(* Logix 5000 project; controller ControlLogix 1756-L63 rev 16.20; software revision 16.04 *)

TASK MainTask (continuous, watchdog 500 ms) : MainProgram

MODULES
   Local : 1756-L63 (ICP 0, rev 16.20)
      EGD : vendor 1 type 0 code 15 (ICP 1, rev 1.1, Output RPI 5 ms)
END_MODULES

TYPE Backplane :   // Values used by program for data transfer operation between the module and the processor.
STRUCT
   LastRead : INT;   // Index of last read block
   LastWrite : INT;   // Index of last write block
   BlockIndex : INT;   // Computed block offset for data table
   StatusIndex : INT;   // Computed block offset for status data
   ReadDataBlkCount : INT;   // Holds the value of the Block Counts of the Read Data Array. Array Size is divided by 200.
   WriteDataBlkCount : INT;   // Holds the value of the Block Counts of the Write Data Array. Array Size is divided by 200.
   RBTSremainder : INT;   // Holds remainder calculation value from the read array.
   WBTSremainder : INT;   // Holds remainder calculation value from the write array.
   ReadDataSizeGet : INT;   // Holds read data array size.
   WriteDataSizeGet : INT;   // Holds write data array size.
END_STRUCT
END_TYPE

TYPE Blk9250Stat :   // Block 9250 Response Block general status
STRUCT
   BlkWriteIDreq : INT;   // Block Write ID Requested
   PassCnt : INT;   // Program Scan Counter
   ProdCodeByte0 : SINT;   // Product code byte 0 of 0 & 1
   ProdCodeByte1 : SINT;   // Product code byte 1 of 0 & 1
   ProdCodeByte2 : SINT;   // Product code byte 2 of 2 & 3
   ProdCodeByte3 : SINT;   // Product code byte 3 of 2 & 3
   RevByte0 : SINT;   // Revision byte 0 of 0 & 1
   RevByte1 : SINT;   // Revision byte 1 of 0 & 1
   RevByte2 : SINT;   // Revision byte 2 of 2 & 3
   RevByte3 : SINT;   // Revision byte 3 of 2 & 3
   OpByte0 : SINT;   // Op byte 0 of 0 & 1
   OpByte1 : SINT;   // Op byte 1 of 0 & 1
   OpByte2 : SINT;   // Op byte 2 of 2 & 3
   OpByte3 : SINT;   // Op byte 3 of 2 & 3
   RunByte0 : SINT;   // Run byte 0 of 0 & 1
   RunByte1 : SINT;   // Run byte 1 of 0 & 1
   RunByte2 : SINT;   // Run byte 2 of 2 & 3
   RunByte3 : SINT;   // Run byte 3 of 2 & 3
   BlkXferStat : BlkStat;   // Block transfer statistics
   ProductCodeName : DINT;   // Product code name
   RevisionLevel : DINT;   // Firmware revision level
   OpSysRevision : DINT;   // Operating system revision level
   RunNumber : DINT;   // Run number
END_STRUCT
END_TYPE

TYPE BlkStat :   // Block Transfer Statistics
STRUCT
   Write : INT;   // Total number of write block transfers. Block Write counter.
   Read : INT;   // Total number of read block transfers. Block Read counter.
   Parse : INT;   // Total number of blocks parsed. Block Parse counter.
   Error : INT;   // Total number of block transfer errors. Block Error Counter.
END_STRUCT
END_TYPE

TYPE CPStat :   // Block 2000 Each Conmsumer/Producer Status Data
STRUCT
   Status : INT;   // Status (0=invalid, 1=producing/healthy, 2=pending/unhealthy)
   StatBit : INT;   // Status bit mapped (bit 0=error or invalid, bit 1=not time synchronized, bits 2 to 15 reserved)
   CPnumTimesLSW : INT;   // Number of times C/P (LSW)
   CPnumTimesMSW : INT;   // Number of times C/P (MSW)
   MissCntLSW : INT;   // Missed count (LSW)
   MissCntMSW : INT;   // Missed count (MSW)
   RfrshCntErrLSW : INT;   // Refresh count error (LSW)
   RfrshCntErrMSW : INT;   // Refresh count error (MSW)
   InvErrBit : INT;   // Invalid error bit set by producer
   TimeSyncErr : INT;   // Time sync error set by producer
   ShrtMEsgErr : INT;   // Short message error in exchange
   LngMEsgErr : INT;   // Long message error in exchange
   PrtclPVN : INT;   // Protocol PVN not set to 1
   CnfgSig : INT;   // Configuration signature not set correctly
   CPMessageCount : DINT;   // Number of times C/P
   MissedCount : DINT;   // Missed count
   RefreshCountErr : DINT;   // Refresh count error
END_STRUCT
END_TYPE

TYPE EGDCONTROL :   // Stores control registers used by the processor to request special tasks from the module.
STRUCT
   ColdBoot : BOOL;   // Total SW/HW module reset
   WarmBoot : BOOL;   // Configuration parameter reset
   CPmessage : CPStat[17];   // CP message status
   CPmessReq : BOOL;   // Initiates Block 2000. C/P Messages
   CPmessReqQty : INT;   // Quantity of Consumer/Producer Message
   CPindxFirst : INT;   // Index of the First Consumer/Producer Message
   CPmessResQty : INT;   // Quantity of Consumer/Producer Message from Module
   CPindxResFirst : INT;   // Index of the First Consumer/Producer Message from Module
   CPwordsQty : INT;   // Calculated words Qty CP messages x 14.
   PortErrors : PortErrors;   // This encapsulates all port error statistics.
END_STRUCT
END_TYPE

TYPE EGDDATA :   // Stores the database (read and write) values.
STRUCT
   ReadData : INT[600];   // Data read from module
   WriteData : INT[600];   // Data to write to module
END_STRUCT
END_TYPE

TYPE EGDMODULEDEF :   // MVI56-EGD module definitions.
STRUCT
   DATA : EGDDATA;   // Stores the database (read and write) values.
   CONTROL : EGDCONTROL;   // Stores control registers used by the processor to request special tasks from the module.
   STATUS : EGDSTATUS;   // Stores status registers.
   UTIL : EGDUTIL;   // Stores tags that are used by the ladder logic for internal processing.
END_STRUCT
END_TYPE

TYPE EGDSTATUS :   // Stores status registers.
STRUCT
   Blk9250GenStat : Blk9250Stat;   // Block 9250 statistics
   BlkStat : BlkStat;   // Block Transfer Statistics
   CPStat : CPStat;   // Block 2000 Each Conmsumer/Producer Status Data
   InStat : InStat;   // Status information in each read block
   SNTPStat : SNTPStat;   // Simple Network Time Protocol statistics.
   GenStatReq : BOOL;   // Initiates Block 9260 C/P Messages
END_STRUCT
END_TYPE

TYPE EGDUTIL :   // Stores tags that are used by the ladder logic for internal processing.
STRUCT
   HaltBlk9250 : BOOL;   // Halts Block 9250
   HaltBlk2000 : BOOL;   // Halts Block 2000
   BP : Backplane;   // Values used by program for data transfer operation between the module and the processor.
END_STRUCT
END_TYPE

TYPE InStat :   // This status data is returned on each read block and can be used to detect proper module operation.
STRUCT
   PassCnt : INT;   // Program cycle/scan counter
   BlkCntr : BlkStat;   // Block counter statistics
   SNTP : SNTPStat;   // Simple Network Time Protocol statistics
END_STRUCT
END_TYPE

TYPE PortErrors :   // This encapsulates all port error statistics.
STRUCT
   CmdReq : INT;   // Total number of command list requests sent
   CmdResp : INT;   // Total number of command list responses received
   CmdErr : INT;   // Total number of command list errors
   Requests : INT;   // Total number of requests for port
   Responses : INT;   // Total number of responses for port
   ErrSent : INT;   // Total number of errors sent
   ErrRec : INT;   // Total number of errors received
   CfgErrWord : INT;   // Configuration Error Word
   CurErr : INT;   // Current Error code
   LastErr : INT;   // Last recorded error code
END_STRUCT
END_TYPE

TYPE SNTPStat :   // Simple Network Time Protocol statistics.
STRUCT
   ValidTime : INT;   // SNTP valid time
   ReqCnt : INT;   // SNTP request count
   RespCnt : INT;   // SNTP response count
   CompCnt : INT;   // SNTP computation count
   SetCnt : INT;   // SNTP set count
   TimeoutErrCnt : INT;   // SNTP timeout error count
   SecLSW : INT;   // SNTP seconds (LSW)
   SecMSW : INT;   // SNTP seconds (MSW)
   micSecLSW : INT;   // SNTP microseconds (LSW)
   micSecMSW : INT;   // SNTP microseconds (MSW)
   Sec : DINT;   // SNTP seconds
   micSec : DINT;   // SNTP microseconds
END_STRUCT
END_TYPE

ADD_ON_INSTRUCTION AOI56EGD   (* revision 1.2, ExecutePrescan *)
// Add-On instruction for the MVI56-EGD module.
// Revision note:
// v1.2 - Removed FLL instruction in PreScan that was clearing WriteData Array in RUN/PROGRAM mode change
VAR_IN_OUT
   Connection_Input : INT[250]; {required}   // Input parameters.
   Connection_Output : INT[248]; {required}   // Output parameters
   EGD : EGDMODULEDEF; {required}
END_VAR
VAR
   MJFaults : DINT[12];
END_VAR

ROUTINE Logic   (* ladder *)
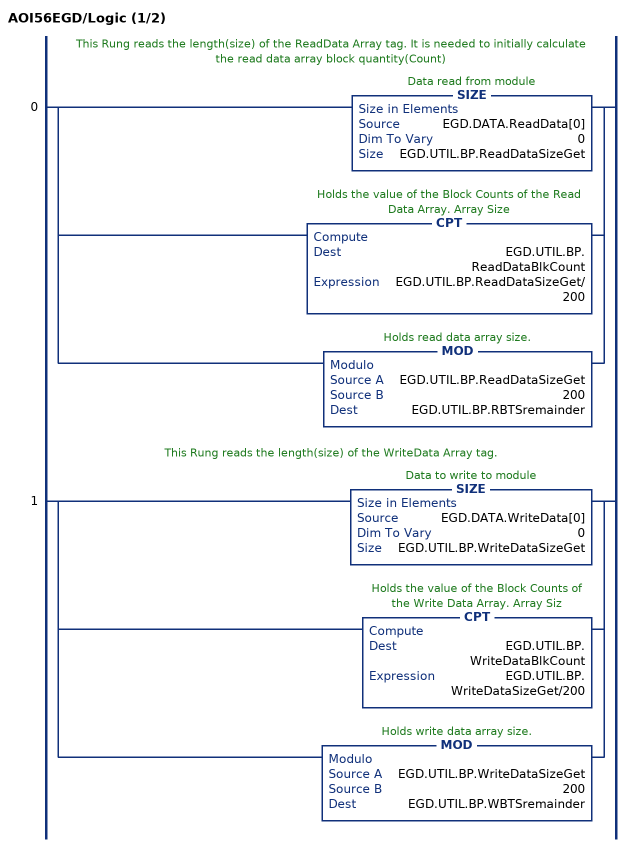
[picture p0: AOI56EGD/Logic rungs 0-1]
   // This Rung reads the length(size) of the ReadData Array tag. It is needed to initially calculate the read data array block quantity(Count)
   0: [SIZE(EGD.DATA.ReadData[0],0,EGD.UTIL.BP.ReadDataSizeGet) ,CPT(EGD.UTIL.BP.ReadDataBlkCount,EGD.UTIL.BP.ReadDataSizeGet/200) ,MOD(EGD.UTIL.BP.ReadDataSizeGet,200,EGD.UTIL.BP.RBTSremainder) ];
   // This Rung reads the length(size) of the WriteData Array tag.
   1: [SIZE(EGD.DATA.WriteData[0],0,EGD.UTIL.BP.WriteDataSizeGet) ,CPT(EGD.UTIL.BP.WriteDataBlkCount,EGD.UTIL.BP.WriteDataSizeGet/200) ,MOD(EGD.UTIL.BP.WriteDataSizeGet,200,EGD.UTIL.BP.WBTSremainder) ];
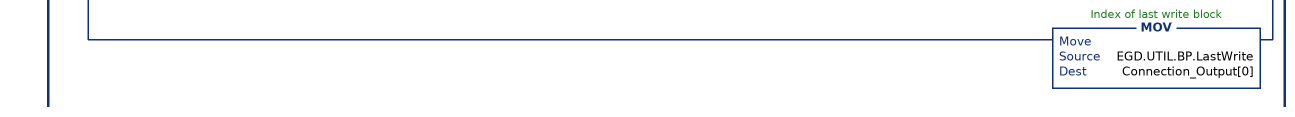
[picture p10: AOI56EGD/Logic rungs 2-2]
   2: NEQ(Connection_Input[249],EGD.UTIL.BP.LastRead)[MOV(Connection_Input[249],EGD.UTIL.BP.LastRead) ,GEQ(EGD.UTIL.BP.LastRead,1) [LEQ(EGD.UTIL.BP.LastRead,EGD.UTIL.BP.ReadDataBlkCount) [CPT(EGD.UTIL.BP.BlockIndex,(EGD.UTIL.BP.LastRead-1)*200) ,COP(Connection_Input[2],EGD.DATA.ReadData[EGD.UTIL.BP.BlockIndex],200) ] ,CMP(EGD.UTIL.BP.LastRead - EGD.UTIL.BP.ReadDataBlkCount = 1) GRT(EGD.UTIL.BP.RBTSremainder,0) [CPT(EGD.UTIL.BP.BlockIndex,(EGD.UTIL.BP.LastRead-1) * 200) ,COP(Connection_Input[2],EGD.DATA.ReadData[EGD.UTIL.BP.BlockIndex],EGD.UTIL.BP.RBTSremainder) ] ] ,[COP(Connection_Input[202],EGD.STATUS.InStat.PassCnt,1) ,COP(Connection_Input[203],EGD.STATUS.InStat.BlkCntr.Write,4) ,COP(Connection_Input[207],EGD.STATUS.InStat.SNTP.ValidTime,10) ,COP(EGD.STATUS.InStat.SNTP.SecLSW,EGD.STATUS.InStat.SNTP.Sec,2) ] ,EQU(EGD.UTIL.BP.LastRead,2000) [MOV(Connection_Input[2],EGD.CONTROL.CPmessResQty) ,MOV(Connection_Input[3],EGD.CONTROL.CPindxResFirst) ,[COP(Connection_Input[4],EGD.CONTROL.CPmessage[0].Status,14) ,COP(EGD.CONTROL.CPmessage[0].CPnumTimesLSW,EGD.CONTROL.CPmessage[0].CPMessageCount,3) ] ,[COP(Connection_Input[18],EGD.CONTROL.CPmessage[1].Status,14) ,COP(EGD.CONTROL.CPmessage[1].CPnumTimesLSW,EGD.CONTROL.CPmessage[1].CPMessageCount,3) ] ,[COP(Connection_Input[32],EGD.CONTROL.CPmessage[2].Status,14) ,COP(EGD.CONTROL.CPmessage[2].CPnumTimesLSW,EGD.CONTROL.CPmessage[2].CPMessageCount,3) ] ,[COP(Connection_Input[46],EGD.CONTROL.CPmessage[3].Status,14) ,COP(EGD.CONTROL.CPmessage[3].CPnumTimesLSW,EGD.CONTROL.CPmessage[3].CPMessageCount,3) ] ,[COP(Connection_Input[60],EGD.CONTROL.CPmessage[4].Status,14) ,COP(EGD.CONTROL.CPmessage[4].CPnumTimesLSW,EGD.CONTROL.CPmessage[4].CPMessageCount,3) ] ,[COP(Connection_Input[74],EGD.CONTROL.CPmessage[5].Status,14) ,COP(EGD.CONTROL.CPmessage[5].CPnumTimesLSW,EGD.CONTROL.CPmessage[5].CPMessageCount,3) ] ,[COP(Connection_Input[88],EGD.CONTROL.CPmessage[6].Status,14) ,COP(EGD.CONTROL.CPmessage[6].CPnumTimesLSW,EGD.CONTROL.CPmessage[6].CPMessageCount,3) ] ,[COP(Connection_Input[102],EGD.CONTROL.CPmessage[7].Status,14) ,COP(EGD.CONTROL.CPmessage[7].CPnumTimesLSW,EGD.CONTROL.CPmessage[7].CPMessageCount,3) ] ,[COP(Connection_Input[116],EGD.CONTROL.CPmessage[8].Status,14) ,COP(EGD.CONTROL.CPmessage[8].CPnumTimesLSW,EGD.CONTROL.CPmessage[8].CPMessageCount,3) ] ,[COP(Connection_Input[130],EGD.CONTROL.CPmessage[9].Status,14) ,COP(EGD.CONTROL.CPmessage[9].CPnumTimesLSW,EGD.CONTROL.CPmessage[9].CPMessageCount,3) ] ,[COP(Connection_Input[144],EGD.CONTROL.CPmessage[10].Status,14) ,COP(EGD.CONTROL.CPmessage[10].CPnumTimesLSW,EGD.CONTROL.CPmessage[10].CPMessageCount,3) ] ,[COP(Connection_Input[158],EGD.CONTROL.CPmessage[11].Status,14) ,COP(EGD.CONTROL.CPmessage[11].CPnumTimesLSW,EGD.CONTROL.CPmessage[11].CPMessageCount,3) ] ,[COP(Connection_Input[172],EGD.CONTROL.CPmessage[12].Status,14) ,COP(EGD.CONTROL.CPmessage[12].CPnumTimesLSW,EGD.CONTROL.CPmessage[12].CPMessageCount,3) ] ,[COP(Connection_Input[186],EGD.CONTROL.CPmessage[13].Status,14) ,COP(EGD.CONTROL.CPmessage[13].CPnumTimesLSW,EGD.CONTROL.CPmessage[13].CPMessageCount,3) ] ,[COP(Connection_Input[200],EGD.CONTROL.CPmessage[14].Status,14) ,COP(EGD.CONTROL.CPmessage[14].CPnumTimesLSW,EGD.CONTROL.CPmessage[14].CPMessageCount,3) ] ,[COP(Connection_Input[214],EGD.CONTROL.CPmessage[15].Status,14) ,COP(EGD.CONTROL.CPmessage[15].CPnumTimesLSW,EGD.CONTROL.CPmessage[15].CPMessageCount,3) ] ,[COP(Connection_Input[228],EGD.CONTROL.CPmessage[16].Status,14) ,COP(EGD.CONTROL.CPmessage[16].CPnumTimesLSW,EGD.CONTROL.CPmessage[16].CPMessageCount,3) ] ,OTU(EGD.UTIL.HaltBlk2000) ] ,EQU(EGD.UTIL.BP.LastRead,9250) [MOV(Connection_Input[1],EGD.STATUS.Blk9250GenStat.BlkWriteIDreq) ,COP(Connection_Input[2],EGD.STATUS.Blk9250GenStat.PassCnt,1) ,[COP(Connection_Input[3],EGD.STATUS.Blk9250GenStat.ProdCodeByte0,16) ,COP(EGD.STATUS.Blk9250GenStat.ProdCodeByte0,EGD.STATUS.Blk9250GenStat.ProductCodeName,4) ,SWPB(EGD.STATUS.Blk9250GenStat.ProductCodeName,REVERSE,EGD.STATUS.Blk9250GenStat.ProductCodeName) ,SWPB(EGD.STATUS.Blk9250GenStat.RevisionLevel,REVERSE,EGD.STATUS.Blk9250GenStat.RevisionLevel) ,SWPB(EGD.STATUS.Blk9250GenStat.OpSysRevision,REVERSE,EGD.STATUS.Blk9250GenStat.OpSysRevision) ,SWPB(EGD.STATUS.Blk9250GenStat.RunNumber,REVERSE,EGD.STATUS.Blk9250GenStat.RunNumber) ] ,COP(Connection_Input[11],EGD.STATUS.Blk9250GenStat.BlkXferStat.Write,4) ,[COP(Connection_Input[15],EGD.STATUS.SNTPStat.ValidTime,10) ,COP(EGD.STATUS.SNTPStat.SecLSW,EGD.STATUS.SNTPStat.Sec,2) ] ,OTU(EGD.UTIL.HaltBlk9250) ] ,MOV(Connection_Input[1],EGD.UTIL.BP.LastWrite) ,XIC(EGD.CONTROL.WarmBoot) [MOV(9998,EGD.UTIL.BP.LastWrite) ,OTU(EGD.CONTROL.WarmBoot) ] ,XIC(EGD.CONTROL.ColdBoot) [MOV(9999,EGD.UTIL.BP.LastWrite) ,OTU(EGD.CONTROL.ColdBoot) ] ,GEQ(EGD.UTIL.BP.LastWrite,1) [LEQ(EGD.UTIL.BP.LastWrite,EGD.UTIL.BP.WriteDataBlkCount) [CPT(EGD.UTIL.BP.BlockIndex,(EGD.UTIL.BP.LastWrite-1)*200) ,COP(EGD.DATA.WriteData[EGD.UTIL.BP.BlockIndex],Connection_Output[1],200) ] ,CMP(EGD.UTIL.BP.LastWrite - EGD.UTIL.BP.WriteDataBlkCount = 1) GRT(EGD.UTIL.BP.WBTSremainder,0) [CPT(EGD.UTIL.BP.BlockIndex,(EGD.UTIL.BP.LastWrite-1)*200) ,COP(EGD.DATA.WriteData[EGD.UTIL.BP.BlockIndex],Connection_Output[1],EGD.UTIL.BP.WBTSremainder) ] ] ,XIC(EGD.CONTROL.CPmessReq) XIO(EGD.UTIL.HaltBlk2000) LIM(0,EGD.CONTROL.CPindxFirst,99) LIM(1,EGD.CONTROL.CPmessReqQty,17) [MOV(EGD.CONTROL.CPmessReqQty,Connection_Output[1]) ,MOV(EGD.CONTROL.CPindxFirst,Connection_Output[2]) ,MOV(2000,EGD.UTIL.BP.LastWrite) ,OTL(EGD.UTIL.HaltBlk2000) ,OTU(EGD.CONTROL.CPmessReq) ] ,XIC(EGD.STATUS.GenStatReq) XIO(EGD.UTIL.HaltBlk9250) [MOV(9250,EGD.UTIL.BP.LastWrite) ,OTL(EGD.UTIL.HaltBlk9250) ,OTU(EGD.STATUS.GenStatReq) ] ,MOV(EGD.UTIL.BP.LastWrite,Connection_Output[0]) ];
END_ROUTINE

ROUTINE Prescan   (* ladder *)
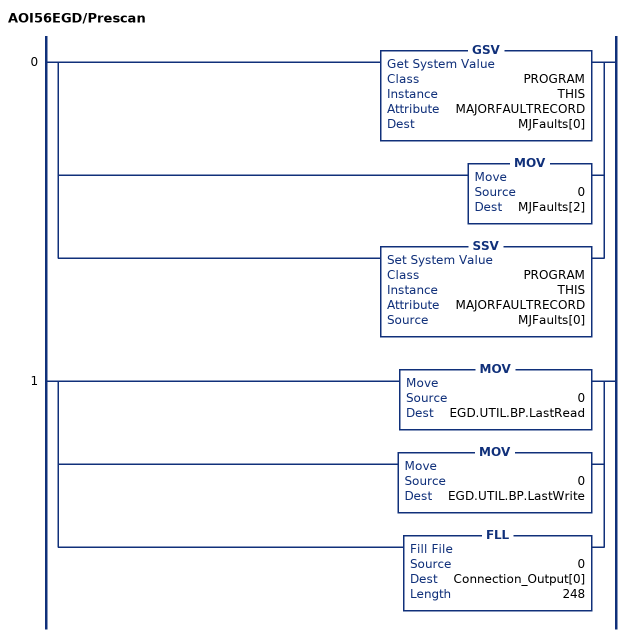
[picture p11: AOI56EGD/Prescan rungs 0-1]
   0: [GSV(PROGRAM,THIS,MAJORFAULTRECORD,MJFaults[0]) ,MOV(0,MJFaults[2]) ,SSV(PROGRAM,THIS,MAJORFAULTRECORD,MJFaults[0]) ];
   1: [MOV(0,EGD.UTIL.BP.LastRead) ,MOV(0,EGD.UTIL.BP.LastWrite) ,FLL(0,Connection_Output[0],248) ];
END_ROUTINE
END_ADD_ON_INSTRUCTION

VAR_GLOBAL   (* controller tags *)
   AOI56EGD : AOI56EGD;
   EGD : EGDMODULEDEF;
END_VAR

PROGRAM MainProgram   (* main routine MainRoutine *)

ROUTINE MainRoutine   (* ladder *)
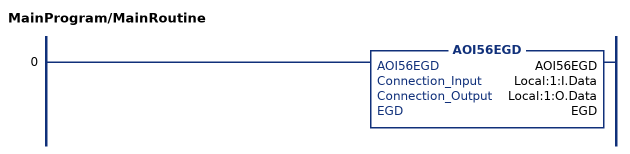
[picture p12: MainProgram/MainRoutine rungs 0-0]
   0: AOI56EGD(AOI56EGD,Local:1:I.Data,Local:1:O.Data,EGD);
END_ROUTINE
END_PROGRAM
